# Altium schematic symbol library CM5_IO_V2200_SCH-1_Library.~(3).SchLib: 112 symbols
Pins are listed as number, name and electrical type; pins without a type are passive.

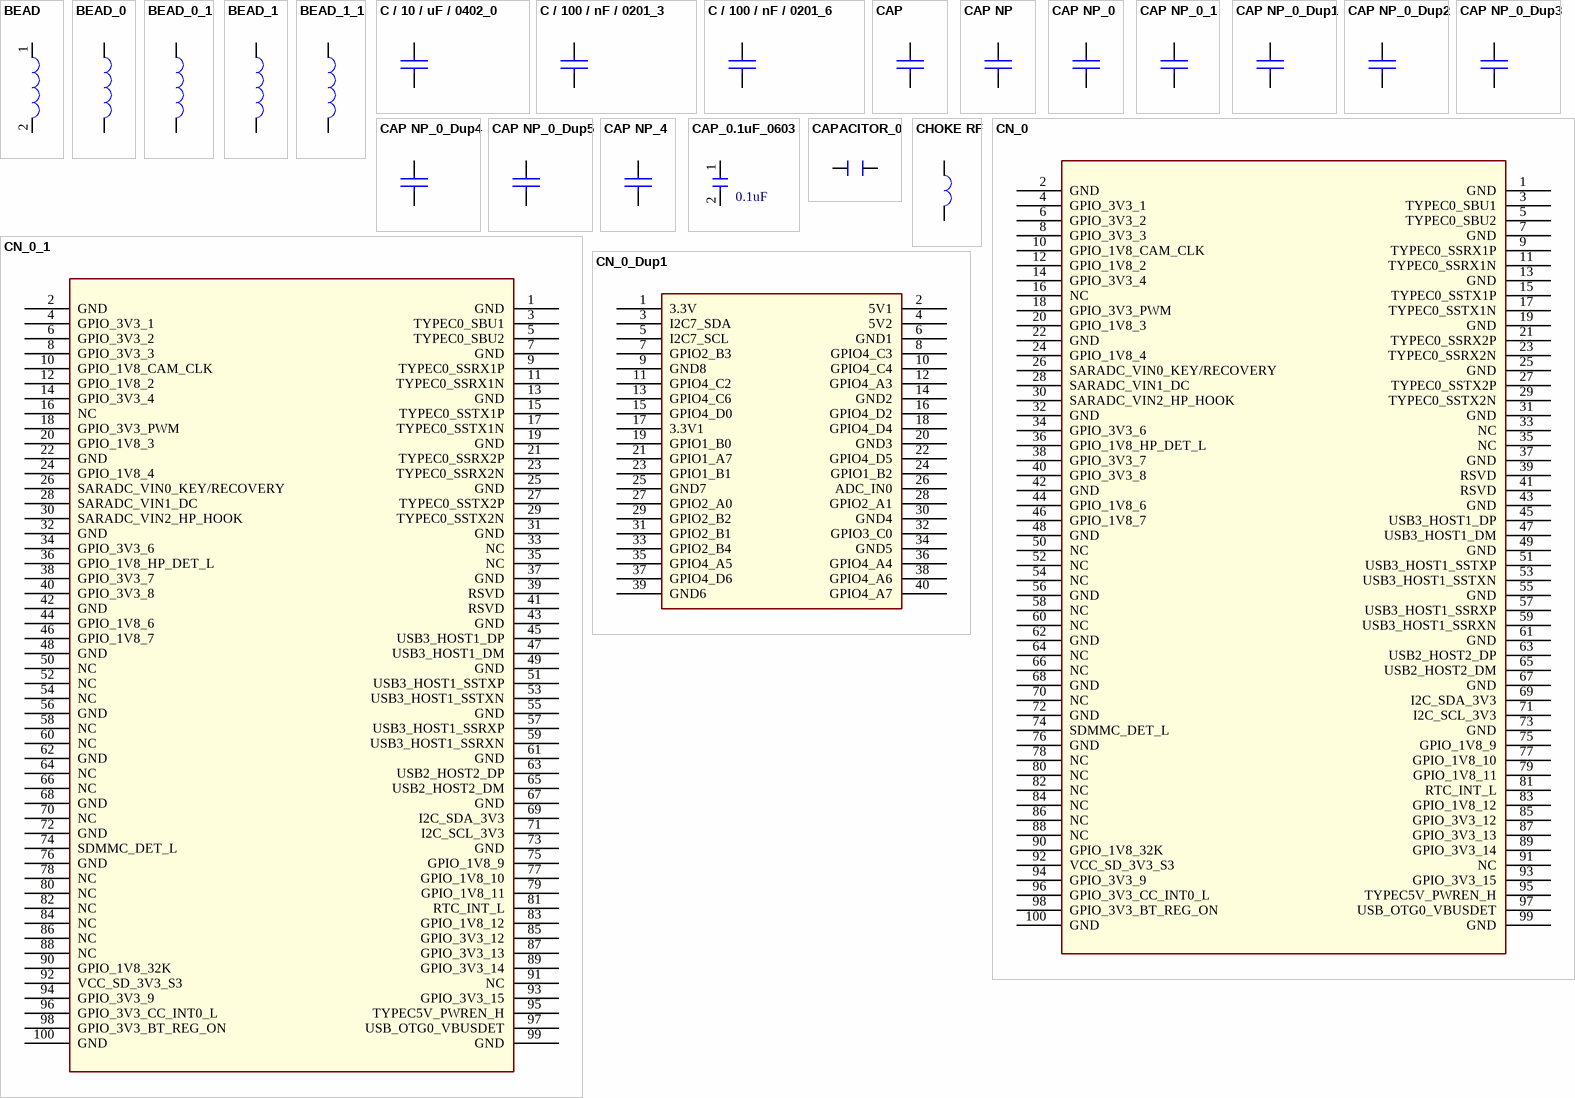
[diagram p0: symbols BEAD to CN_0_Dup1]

## BEAD
designator FB?
Altium-Right: 20; Altium-Bottom: 40
pins: 1, 2

## BEAD_0
designator FB?
Altium-Right: 20; Altium-Bottom: 40
pins: 1, 2

## BEAD_0_1
designator FB?
Altium-Right: 20; Altium-Bottom: 40
pins: 1, 2

## BEAD_1
designator FB?
Altium-Right: 20; Altium-Bottom: 40
pins: 1, 2

## BEAD_1_1
designator FB?
Altium-Right: 20; Altium-Bottom: 40
pins: 1, 2

## C / 10 / uF / 0402_0
designator C?
Altium-Right: 20; Altium-Bottom: 10
footprint C0402
pins: 1, 2

## C / 100 / nF / 0201_3
designator C?
Altium-Right: 20; Altium-Bottom: 10
footprint C0201
pins: 1, 2

## C / 100 / nF / 0201_6
designator C?
Altium-Right: 20; Altium-Bottom: 10
footprint C0201
pins: 1, 2

## CAP
designator C?
Altium-Right: 20; Altium-Bottom: 10
pins: 1, 2

## CAP NP
designator C?
Altium-Right: 20; Altium-Bottom: 10
footprint C0402
pins: 1, 2

## CAP NP_0
designator C?
Altium-Right: 20; Altium-Bottom: 10
pins: 1, 2

## CAP NP_0_1
designator C?
Altium-Right: 20; Altium-Bottom: 10
pins: 1, 2

## CAP NP_0_Dup1
designator C?
Altium-Right: 20; Altium-Bottom: 10
pins: 1, 2

## CAP NP_0_Dup2
designator C?
Altium-Right: 20; Altium-Bottom: 10
pins: 1, 2

## CAP NP_0_Dup3
designator C?
Altium-Right: 20; Altium-Bottom: 10
pins: 1, 2

## CAP NP_0_Dup4
designator C?
Altium-Right: 20; Altium-Bottom: 10
pins: 1, 2

## CAP NP_0_Dup5
designator C?
Altium-Right: 20; Altium-Bottom: 10
pins: 1, 2

## CAP NP_4
designator C?
Altium-Right: 20; Altium-Bottom: 10
pins: 1, 2

## CAP_0.1uF_0603
designator CB?, comment 0.1uF
Altium-Right: 20; Altium-Bottom: 10
footprint C0603
pins: 1, 2

## CAPACITOR_0
designator C?
Altium-Right: 10; Altium-Bottom: 20
pins: 1, 2

## CHOKE RF
designator L?
Altium-Right: 20
pins: 1, 2

## CN_0
designator CN?
Altium-Right: 296; Altium-Bottom: 529
pins: 1 GND, 2 GND, 3 TYPEC0_SBU1, 4 GPIO_3V3_1, 5 TYPEC0_SBU2, 6 GPIO_3V3_2, 7 GND, 8 GPIO_3V3_3, 9 TYPEC0_SSRX1P, 10 GPIO_1V8_CAM_CLK, 11 TYPEC0_SSRX1N, 12 GPIO_1V8_2, 13 GND, 14 GPIO_3V3_4, 15 TYPEC0_SSTX1P, 16 NC, 17 TYPEC0_SSTX1N, 18 GPIO_3V3_PWM, 19 GND, 20 GPIO_1V8_3, 21 TYPEC0_SSRX2P, 22 GND, 23 TYPEC0_SSRX2N, 24 GPIO_1V8_4, 25 GND, 26 SARADC_VIN0_KEY/RECOVERY, 27 TYPEC0_SSTX2P, 28 SARADC_VIN1_DC, 29 TYPEC0_SSTX2N, 30 SARADC_VIN2_HP_HOOK, 31 GND, 32 GND, 33 NC, 34 GPIO_3V3_6, 35 NC, 36 GPIO_1V8_HP_DET_L, 37 GND, 38 GPIO_3V3_7, 39 RSVD, 40 GPIO_3V3_8, 41 RSVD, 42 GND, 43 GND, 44 GPIO_1V8_6, 45 USB3_HOST1_DP, 46 GPIO_1V8_7, 47 USB3_HOST1_DM, 48 GND, 49 GND, 50 NC, 51 USB3_HOST1_SSTXP, 52 NC, 53 USB3_HOST1_SSTXN, 54 NC, 55 GND, 56 GND, 57 USB3_HOST1_SSRXP, 58 NC, 59 USB3_HOST1_SSRXN, 60 NC, 61 GND, 62 GND, 63 USB2_HOST2_DP, 64 NC, 65 USB2_HOST2_DM, 66 NC, 67 GND, 68 GND, 69 I2C_SDA_3V3, 70 NC, 71 I2C_SCL_3V3, 72 GND, 73 GND, 74 SDMMC_DET_L, 75 GPIO_1V8_9, 76 GND, 77 GPIO_1V8_10, 78 NC, 79 GPIO_1V8_11, 80 NC, 81 RTC_INT_L, 82 NC, 83 GPIO_1V8_12, 84 NC, 85 GPIO_3V3_12, 86 NC, 87 GPIO_3V3_13, 88 NC, 89 GPIO_3V3_14, 90 GPIO_1V8_32K, 91 NC, 92 VCC_SD_3V3_S3, 93 GPIO_3V3_15, 94 GPIO_3V3_9, 95 TYPEC5V_PWREN_H, 96 GPIO_3V3_CC_INT0_L, 97 USB_OTG0_VBUSDET, 98 GPIO_3V3_BT_REG_ON, 99 GND, 100 GND

## CN_0_1
designator CN?
Altium-Right: 296; Altium-Bottom: 529
pins: 1 GND, 2 GND, 3 TYPEC0_SBU1, 4 GPIO_3V3_1, 5 TYPEC0_SBU2, 6 GPIO_3V3_2, 7 GND, 8 GPIO_3V3_3, 9 TYPEC0_SSRX1P, 10 GPIO_1V8_CAM_CLK, 11 TYPEC0_SSRX1N, 12 GPIO_1V8_2, 13 GND, 14 GPIO_3V3_4, 15 TYPEC0_SSTX1P, 16 NC, 17 TYPEC0_SSTX1N, 18 GPIO_3V3_PWM, 19 GND, 20 GPIO_1V8_3, 21 TYPEC0_SSRX2P, 22 GND, 23 TYPEC0_SSRX2N, 24 GPIO_1V8_4, 25 GND, 26 SARADC_VIN0_KEY/RECOVERY, 27 TYPEC0_SSTX2P, 28 SARADC_VIN1_DC, 29 TYPEC0_SSTX2N, 30 SARADC_VIN2_HP_HOOK, 31 GND, 32 GND, 33 NC, 34 GPIO_3V3_6, 35 NC, 36 GPIO_1V8_HP_DET_L, 37 GND, 38 GPIO_3V3_7, 39 RSVD, 40 GPIO_3V3_8, 41 RSVD, 42 GND, 43 GND, 44 GPIO_1V8_6, 45 USB3_HOST1_DP, 46 GPIO_1V8_7, 47 USB3_HOST1_DM, 48 GND, 49 GND, 50 NC, 51 USB3_HOST1_SSTXP, 52 NC, 53 USB3_HOST1_SSTXN, 54 NC, 55 GND, 56 GND, 57 USB3_HOST1_SSRXP, 58 NC, 59 USB3_HOST1_SSRXN, 60 NC, 61 GND, 62 GND, 63 USB2_HOST2_DP, 64 NC, 65 USB2_HOST2_DM, 66 NC, 67 GND, 68 GND, 69 I2C_SDA_3V3, 70 NC, 71 I2C_SCL_3V3, 72 GND, 73 GND, 74 SDMMC_DET_L, 75 GPIO_1V8_9, 76 GND, 77 GPIO_1V8_10, 78 NC, 79 GPIO_1V8_11, 80 NC, 81 RTC_INT_L, 82 NC, 83 GPIO_1V8_12, 84 NC, 85 GPIO_3V3_12, 86 NC, 87 GPIO_3V3_13, 88 NC, 89 GPIO_3V3_14, 90 GPIO_1V8_32K, 91 NC, 92 VCC_SD_3V3_S3, 93 GPIO_3V3_15, 94 GPIO_3V3_9, 95 TYPEC5V_PWREN_H, 96 GPIO_3V3_CC_INT0_L, 97 USB_OTG0_VBUSDET, 98 GPIO_3V3_BT_REG_ON, 99 GND, 100 GND

## CN_0_Dup1
designator CN?
Altium-Right: 160; Altium-Bottom: 210
pins: 1 3.3V, 2 5V1, 3 I2C7_SDA, 4 5V2, 5 I2C7_SCL, 6 GND1, 7 GPIO2_B3, 8 GPIO4_C3, 9 GND8, 10 GPIO4_C4, 11 GPIO4_C2, 12 GPIO4_A3, 13 GPIO4_C6, 14 GND2, 15 GPIO4_D0, 16 GPIO4_D2, 17 3.3V1, 18 GPIO4_D4, 19 GPIO1_B0, 20 GND3, 21 GPIO1_A7, 22 GPIO4_D5, 23 GPIO1_B1, 24 GPIO1_B2, 25 GND7, 26 ADC_IN0, 27 GPIO2_A0, 28 GPIO2_A1, 29 GPIO2_B2, 30 GND4, 31 GPIO2_B1, 32 GPIO3_C0, 33 GPIO2_B4, 34 GND5, 35 GPIO4_A5, 36 GPIO4_A4, 37 GPIO4_D6, 38 GPIO4_A6, 39 GND6, 40 GPIO4_A7

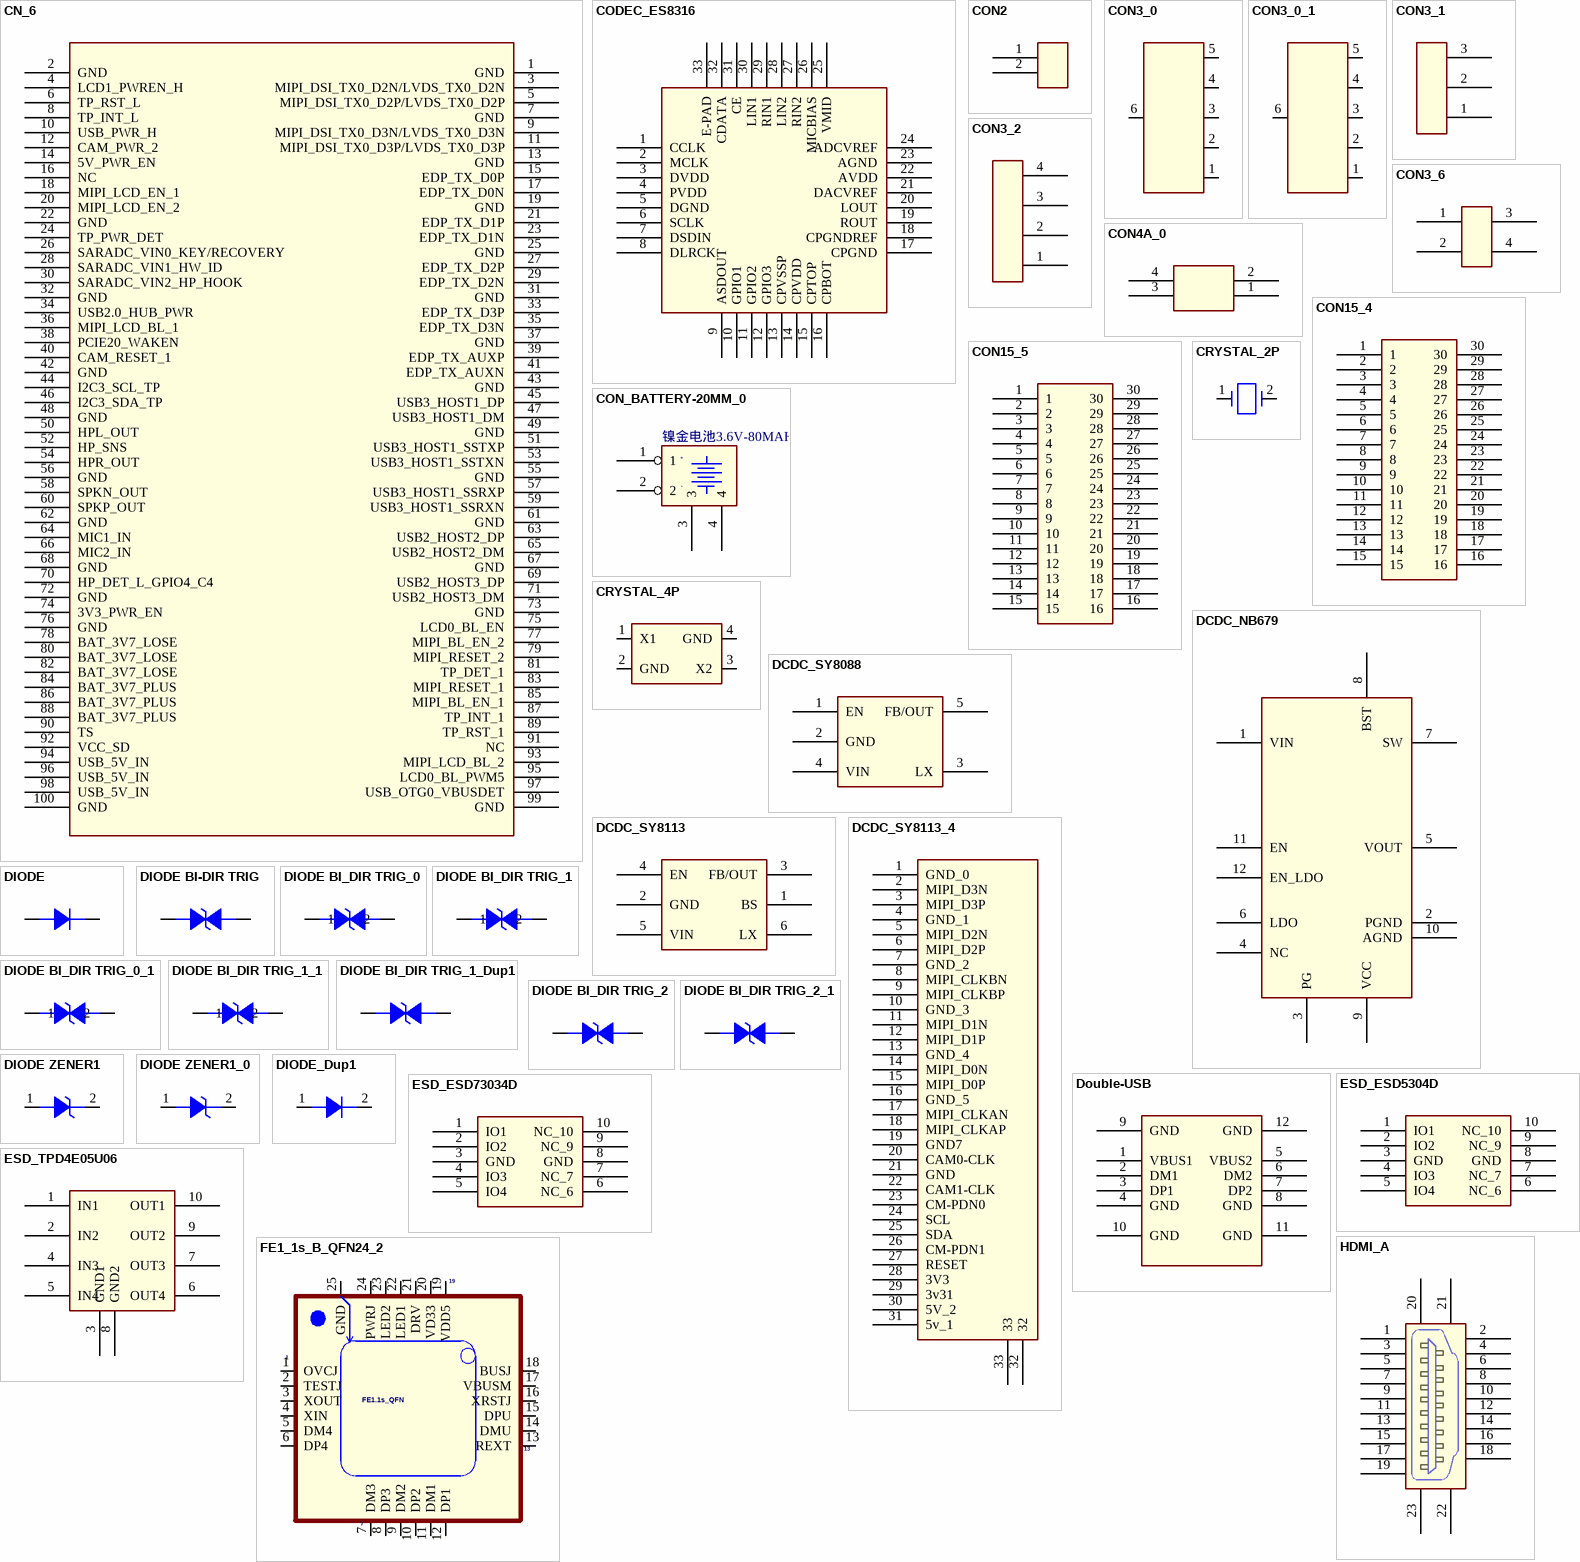
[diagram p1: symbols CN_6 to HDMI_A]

## CN_6
designator CN?
Altium-Right: 296; Altium-Bottom: 529
pins: 1 GND, 2 GND, 3 MIPI_DSI_TX0_D2N/LVDS_TX0_D2N, 4 LCD1_PWREN_H, 5 MIPI_DSI_TX0_D2P/LVDS_TX0_D2P, 6 TP_RST_L, 7 GND, 8 TP_INT_L, 9 MIPI_DSI_TX0_D3N/LVDS_TX0_D3N, 10 USB_PWR_H, 11 MIPI_DSI_TX0_D3P/LVDS_TX0_D3P, 12 CAM_PWR_2, 13 GND, 14 5V_PWR_EN, 15 EDP_TX_D0P, 16 NC, 17 EDP_TX_D0N, 18 MIPI_LCD_EN_1, 19 GND, 20 MIPI_LCD_EN_2, 21 EDP_TX_D1P, 22 GND, 23 EDP_TX_D1N, 24 TP_PWR_DET, 25 GND, 26 SARADC_VIN0_KEY/RECOVERY, 27 EDP_TX_D2P, 28 SARADC_VIN1_HW_ID, 29 EDP_TX_D2N, 30 SARADC_VIN2_HP_HOOK, 31 GND, 32 GND, 33 EDP_TX_D3P, 34 USB2.0_HUB_PWR, 35 EDP_TX_D3N, 36 MIPI_LCD_BL_1, 37 GND, 38 PCIE20_WAKEN, 39 EDP_TX_AUXP, 40 CAM_RESET_1, 41 EDP_TX_AUXN, 42 GND, 43 GND, 44 I2C3_SCL_TP, 45 USB3_HOST1_DP, 46 I2C3_SDA_TP, 47 USB3_HOST1_DM, 48 GND, 49 GND, 50 HPL_OUT, 51 USB3_HOST1_SSTXP, 52 HP_SNS, 53 USB3_HOST1_SSTXN, 54 HPR_OUT, 55 GND, 56 GND, 57 USB3_HOST1_SSRXP, 58 SPKN_OUT, 59 USB3_HOST1_SSRXN, 60 SPKP_OUT, 61 GND, 62 GND, 63 USB2_HOST2_DP, 64 MIC1_IN, 65 USB2_HOST2_DM, 66 MIC2_IN, 67 GND, 68 GND, 69 USB2_HOST3_DP, 70 HP_DET_L_GPIO4_C4, 71 USB2_HOST3_DM, 72 GND, 73 GND, 74 3V3_PWR_EN, 75 LCD0_BL_EN, 76 GND, 77 MIPI_BL_EN_2, 78 BAT_3V7_LOSE, 79 MIPI_RESET_2, 80 BAT_3V7_LOSE, 81 TP_DET_1, 82 BAT_3V7_LOSE, 83 MIPI_RESET_1, 84 BAT_3V7_PLUS, 85 MIPI_BL_EN_1, 86 BAT_3V7_PLUS, 87 TP_INT_1, 88 BAT_3V7_PLUS, 89 TP_RST_1, 90 TS, 91 NC, 92 VCC_SD, 93 MIPI_LCD_BL_2, 94 USB_5V_IN, 95 LCD0_BL_PWM5, 96 USB_5V_IN, 97 USB_OTG0_VBUSDET, 98 USB_5V_IN, 99 GND, 100 GND

## CODEC_ES8316
designator U?
Altium-Right: 150
pins: 1 CCLK, 2 MCLK, 3 DVDD, 4 PVDD, 5 DGND, 6 SCLK, 7 DSDIN, 8 DLRCK, 9 ASDOUT, 10 GPIO1, 11 GPIO2, 12 GPIO3, 13 CPVSSP, 14 CPVDD, 15 CPTOP, 16 CPBOT, 17 CPGND, 18 CPGNDREF, 19 ROUT, 20 LOUT, 21 DACVREF, 22 AVDD, 23 AGND, 24 ADCVREF, 25 VMID, 26 MICBIAS, 27 RIN2, 28 LIN2, 29 RIN1, 30 LIN1, 31 CE, 32 CDATA, 33 E-PAD

## CON2
designator J?
Altium-Right: 20; Altium-Bottom: 30
pins: 1, 2

## CON3_0
designator J?
Altium-Right: 40; Altium-Bottom: 100
pins: 1, 2, 3, 4, 5, 6

## CON3_0_1
designator J?
Altium-Right: 40; Altium-Bottom: 100
pins: 1, 2, 3, 4, 5, 6

## CON3_1
designator J?
Altium-Right: 20; Altium-Bottom: 61
pins: 1, 2, 3

## CON3_2
designator J?
Altium-Right: 20; Altium-Bottom: 81
pins: 1, 2, 3, 4

## CON3_6
designator J?
Altium-Right: 20; Altium-Bottom: 40
pins: 1, 2, 3, 4

## CON4A_0
designator J?
Altium-Right: 40; Altium-Bottom: 30
pins: 1, 2, 3, 4

## CON15_4
designator J?
Altium-Right: 50; Altium-Bottom: 160
pins: 1, 2, 3, 4, 5, 6, 7, 8, 9, 10, 11, 12, 13, 14, 15, 16, 17, 18, 19, 20, 21, 22, 23, 24, 25, 26, 27, 28, 29, 30

## CON15_5
designator J?
Altium-Right: 50; Altium-Bottom: 160
pins: 1, 2, 3, 4, 5, 6, 7, 8, 9, 10, 11, 12, 13, 14, 15, 16, 17, 18, 19, 20, 21, 22, 23, 24, 25, 26, 27, 28, 29, 30

## CON_BATTERY-20MM_0
designator U?, comment 镍金电池3.6V-80MAH
Altium-Right: 50; Altium-Bottom: 40
footprint BATTERY-20MM
pins: 1, 2, 3, 4

## CRYSTAL_2P
designator Y?
Altium-Right: 20
pins: 1, 2

## CRYSTAL_4P
designator Y?
Altium-Right: 60; Altium-Bottom: 40
footprint CRY-3225
pins: 1 X1, 2 GND (power), 3 X2, 4 GND (power)

## DCDC_NB679
designator U?
Altium-Right: 100; Altium-Bottom: 200
footprint QFN12_3R00X2R00X0R90
pins: 1 VIN, 2 PGND, 3 PG, 4 NC, 5 VOUT, 6 LDO, 7 SW, 8 BST, 9 VCC, 10 AGND, 11 EN, 12 EN_LDO

## DCDC_SY8088
designator U?
Altium-Right: 70; Altium-Bottom: 60
pins: 1 EN, 2 GND, 3 LX, 4 VIN, 5 FB/OUT

## DCDC_SY8113
designator U?
Altium-Right: 70; Altium-Bottom: 60
pins: 1 BS, 2 GND, 3 FB/OUT, 4 EN, 5 VIN, 6 LX

## DCDC_SY8113_4
designator U?
Altium-Right: 80; Altium-Bottom: 320
pins: 1 GND_0, 2 MIPI_D3N, 3 MIPI_D3P, 4 GND_1, 5 MIPI_D2N, 6 MIPI_D2P, 7 GND_2, 8 MIPI_CLKBN, 9 MIPI_CLKBP, 10 GND_3, 11 MIPI_D1N, 12 MIPI_D1P, 13 GND_4, 14 MIPI_D0N, 15 MIPI_D0P, 16 GND_5, 17 MIPI_CLKAN, 18 MIPI_CLKAP, 19 GND7, 20 CAM0-CLK, 21 GND, 22 CAM1-CLK, 23 CM-PDN0, 24 SCL, 25 SDA, 26 CM-PDN1, 27 RESET, 28 3V3, 29 3v31, 30 5V_2, 31 5v_1, 32, 33

## DIODE
designator D?
Altium-Right: 30; Altium-Bottom: 20
pins: 1 A, 2 K

## DIODE BI-DIR TRIG
designator D?
Altium-Right: 40; Altium-Bottom: 20
pins: 1, 2

## DIODE BI_DIR TRIG_0
designator ED?
Altium-Right: 40; Altium-Bottom: 20
pins: 1, 2

## DIODE BI_DIR TRIG_0_1
designator ED?
Altium-Right: 40; Altium-Bottom: 20
pins: 1, 2

## DIODE BI_DIR TRIG_1
designator ED?
Altium-Right: 40; Altium-Bottom: 20
pins: 1, 2

## DIODE BI_DIR TRIG_1_1
designator ED?
Altium-Right: 40; Altium-Bottom: 20
pins: 1, 2

## DIODE BI_DIR TRIG_1_Dup1
designator ED?
Altium-Right: 40; Altium-Bottom: 20
pins: 1, 2

## DIODE BI_DIR TRIG_2
designator ED?
Altium-Right: 40; Altium-Bottom: 20
pins: 1, 2

## DIODE BI_DIR TRIG_2_1
designator ED?
Altium-Right: 40; Altium-Bottom: 20
pins: 1, 2

## DIODE ZENER1
designator D?
Altium-Right: 30; Altium-Bottom: 20
pins: 1 ANODE, 2 CATHODE

## DIODE ZENER1_0
designator D?
Altium-Right: 30; Altium-Bottom: 20
pins: 1 ANODE, 2 CATHODE

## DIODE_Dup1
designator D?
Altium-Right: 30; Altium-Bottom: 20
pins: 1 A, 2 K

## Double-USB
designator U?
Altium-Right: 80; Altium-Bottom: 100
footprint USB_DUAL
pins: 1 VBUS1, 2 DM1, 3 DP1, 4 GND, 5 VBUS2, 6 DM2, 7 DP2, 8 GND, 9 GND, 10 GND, 11 GND, 12 GND

## ESD_ESD5304D
designator U?
Altium-Right: 70; Altium-Bottom: 60
pins: 1 IO1, 2 IO2, 3 GND (power), 4 IO3, 5 IO4, 6 NC_6, 7 NC_7, 8 GND (power), 9 NC_9, 10 NC_10

## ESD_ESD73034D
designator U?
Altium-Right: 70; Altium-Bottom: 60
pins: 1 IO1, 2 IO2, 3 GND (power), 4 IO3, 5 IO4, 6 NC_6, 7 NC_7, 8 GND (power), 9 NC_9, 10 NC_10

## ESD_TPD4E05U06
designator U?
Altium-Right: 70; Altium-Bottom: 80
pins: 1 IN1, 2 IN2, 3 GND1, 4 IN3, 5 IN4, 6 OUT4, 7 OUT3, 8 GND2, 9 OUT2, 10 OUT1

## FE1_1s_B_QFN24_2
designator U?, comment FE1.1s_QFN
Altium-Right: 150
pins: 1 OVCJ, 2 TESTJ, 3 XOUT, 4 XIN, 5 DM4, 6 DP4, 7 DM3, 8 DP3, 9 DM2, 10 DP2, 11 DM1, 12 DP1, 13 REXT, 14 DMU, 15 DPU, 16 XRSTJ, 17 VBUSM, 18 BUSJ, 19 VDD5, 20 VD33, 21 DRV, 22 LED1, 23 LED2, 24 PWRJ, 25 GND (power)

## HDMI_A
designator J?
Altium-Right: 40; Altium-Bottom: 110
pins: 1 $PIN0, 2, 3, 4, 5, 6, 7, 8, 9, 10, 11, 12, 13, 14, 15, 16, 17, 18, 19, 20, 21, 22, 23

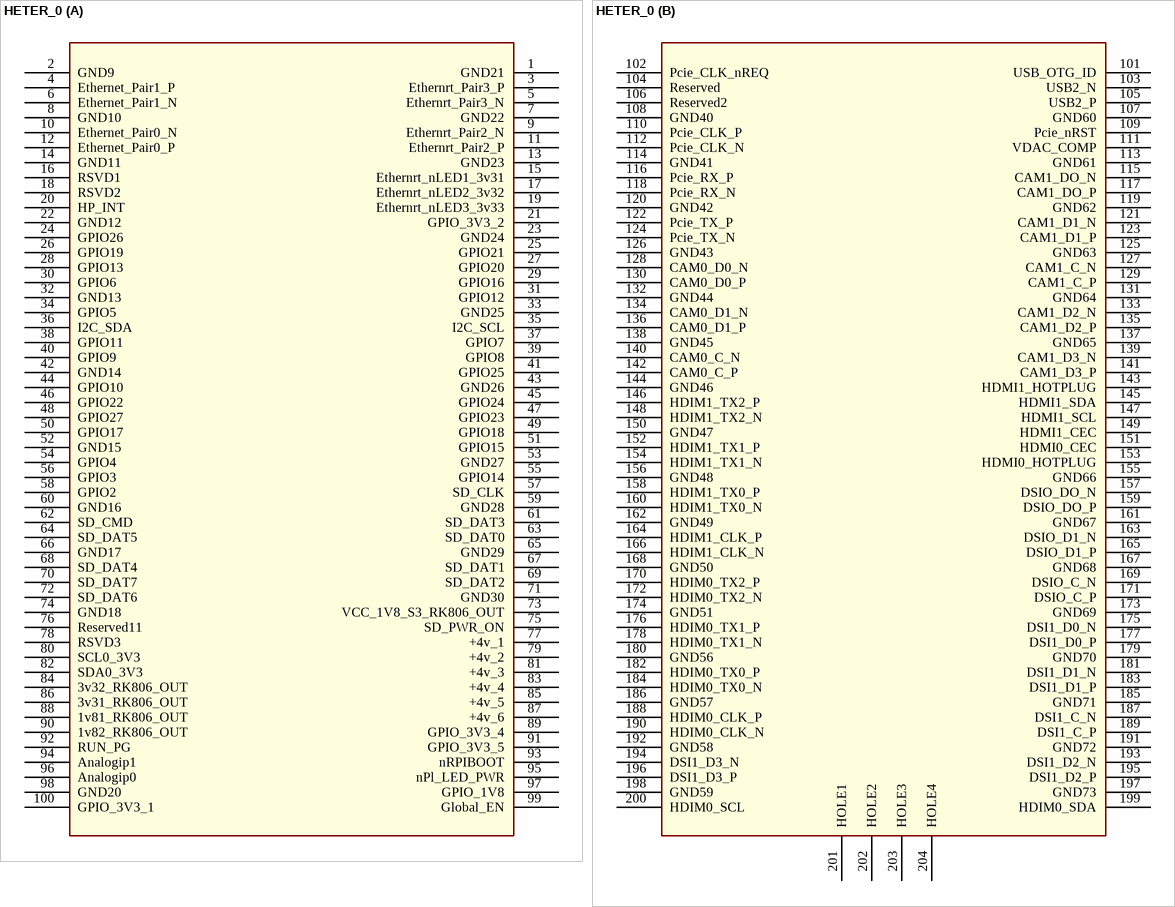
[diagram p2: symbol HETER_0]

## HETER_0
designator U?
Altium-Right: 296; Altium-Bottom: 529
part A pins: 1 GND21, 2 GND9, 3 Ethernrt_Pair3_P, 4 Ethernet_Pair1_P, 5 Ethernrt_Pair3_N, 6 Ethernet_Pair1_N, 7 GND22, 8 GND10, 9 Ethernrt_Pair2_N, 10 Ethernet_Pair0_N, 11 Ethernrt_Pair2_P, 12 Ethernet_Pair0_P, 13 GND23, 14 GND11, 15 Ethernrt_nLED1_3v31, 16 RSVD1, 17 Ethernrt_nLED2_3v32, 18 RSVD2, 19 Ethernrt_nLED3_3v33, 20 HP_INT, 21 GPIO_3V3_2, 22 GND12, 23 GND24, 24 GPIO26, 25 GPIO21, 26 GPIO19, 27 GPIO20, 28 GPIO13, 29 GPIO16, 30 GPIO6, 31 GPIO12, 32 GND13, 33 GND25, 34 GPIO5, 35 I2C_SCL, 36 I2C_SDA, 37 GPIO7, 38 GPIO11, 39 GPIO8, 40 GPIO9, 41 GPIO25, 42 GND14, 43 GND26, 44 GPIO10, 45 GPIO24, 46 GPIO22, 47 GPIO23, 48 GPIO27, 49 GPIO18, 50 GPIO17, 51 GPIO15, 52 GND15, 53 GND27, 54 GPIO4, 55 GPIO14, 56 GPIO3, 57 SD_CLK, 58 GPIO2, 59 GND28, 60 GND16, 61 SD_DAT3, 62 SD_CMD, 63 SD_DAT0, 64 SD_DAT5, 65 GND29, 66 GND17, 67 SD_DAT1, 68 SD_DAT4, 69 SD_DAT2, 70 SD_DAT7, 71 GND30, 72 SD_DAT6, 73 VCC_1V8_S3_RK806_OUT, 74 GND18, 75 SD_PWR_ON, 76 Reserved11, 77 +4v_1, 78 RSVD3, 79 +4v_2, 80 SCL0_3V3, 81 +4v_3, 82 SDA0_3V3, 83 +4v_4, 84 3v32_RK806_OUT, 85 +4v_5, 86 3v31_RK806_OUT, 87 +4v_6, 88 1v81_RK806_OUT, 89 GPIO_3V3_4, 90 1v82_RK806_OUT, 91 GPIO_3V3_5, 92 RUN_PG, 93 nRPIBOOT, 94 Analogip1, 95 nPl_LED_PWR, 96 Analogip0, 97 GPIO_1V8, 98 GND20, 99 Global_EN, 100 GPIO_3V3_1
part B pins: 101 USB_OTG_ID, 102 Pcie_CLK_nREQ, 103 USB2_N, 104 Reserved, 105 USB2_P, 106 Reserved2, 107 GND60, 108 GND40, 109 Pcie_nRST, 110 Pcie_CLK_P, 111 VDAC_COMP, 112 Pcie_CLK_N, 113 GND61, 114 GND41, 115 CAM1_DO_N, 116 Pcie_RX_P, 117 CAM1_DO_P, 118 Pcie_RX_N, 119 GND62, 120 GND42, 121 CAM1_D1_N, 122 Pcie_TX_P, 123 CAM1_D1_P, 124 Pcie_TX_N, 125 GND63, 126 GND43, 127 CAM1_C_N, 128 CAM0_D0_N, 129 CAM1_C_P, 130 CAM0_D0_P, 131 GND64, 132 GND44, 133 CAM1_D2_N, 134 CAM0_D1_N, 135 CAM1_D2_P, 136 CAM0_D1_P, 137 GND65, 138 GND45, 139 CAM1_D3_N, 140 CAM0_C_N, 141 CAM1_D3_P, 142 CAM0_C_P, 143 HDMI1_HOTPLUG, 144 GND46, 145 HDMI1_SDA, 146 HDIM1_TX2_P, 147 HDMI1_SCL, 148 HDIM1_TX2_N, 149 HDMI1_CEC, 150 GND47, 151 HDMI0_CEC, 152 HDIM1_TX1_P, 153 HDMI0_HOTPLUG, 154 HDIM1_TX1_N, 155 GND66, 156 GND48, 157 DSIO_DO_N, 158 HDIM1_TX0_P, 159 DSIO_DO_P, 160 HDIM1_TX0_N, 161 GND67, 162 GND49, 163 DSIO_D1_N, 164 HDIM1_CLK_P, 165 DSIO_D1_P, 166 HDIM1_CLK_N, 167 GND68, 168 GND50, 169 DSIO_C_N, 170 HDIM0_TX2_P, 171 DSIO_C_P, 172 HDIM0_TX2_N, 173 GND69, 174 GND51, 175 DSI1_D0_N, 176 HDIM0_TX1_P, 177 DSI1_D0_P, 178 HDIM0_TX1_N, 179 GND70, 180 GND56, 181 DSI1_D1_N, 182 HDIM0_TX0_P, 183 DSI1_D1_P, 184 HDIM0_TX0_N, 185 GND71, 186 GND57, 187 DSI1_C_N, 188 HDIM0_CLK_P, 189 DSI1_C_P, 190 HDIM0_CLK_N, 191 GND72, 192 GND58, 193 DSI1_D2_N, 194 DSI1_D3_N, 195 DSI1_D2_P, 196 DSI1_D3_P, 197 GND73, 198 GND59, 199 HDIM0_SDA, 200 HDIM0_SCL, 201 HOLE1, 202 HOLE2, 203 HOLE3, 204 HOLE4

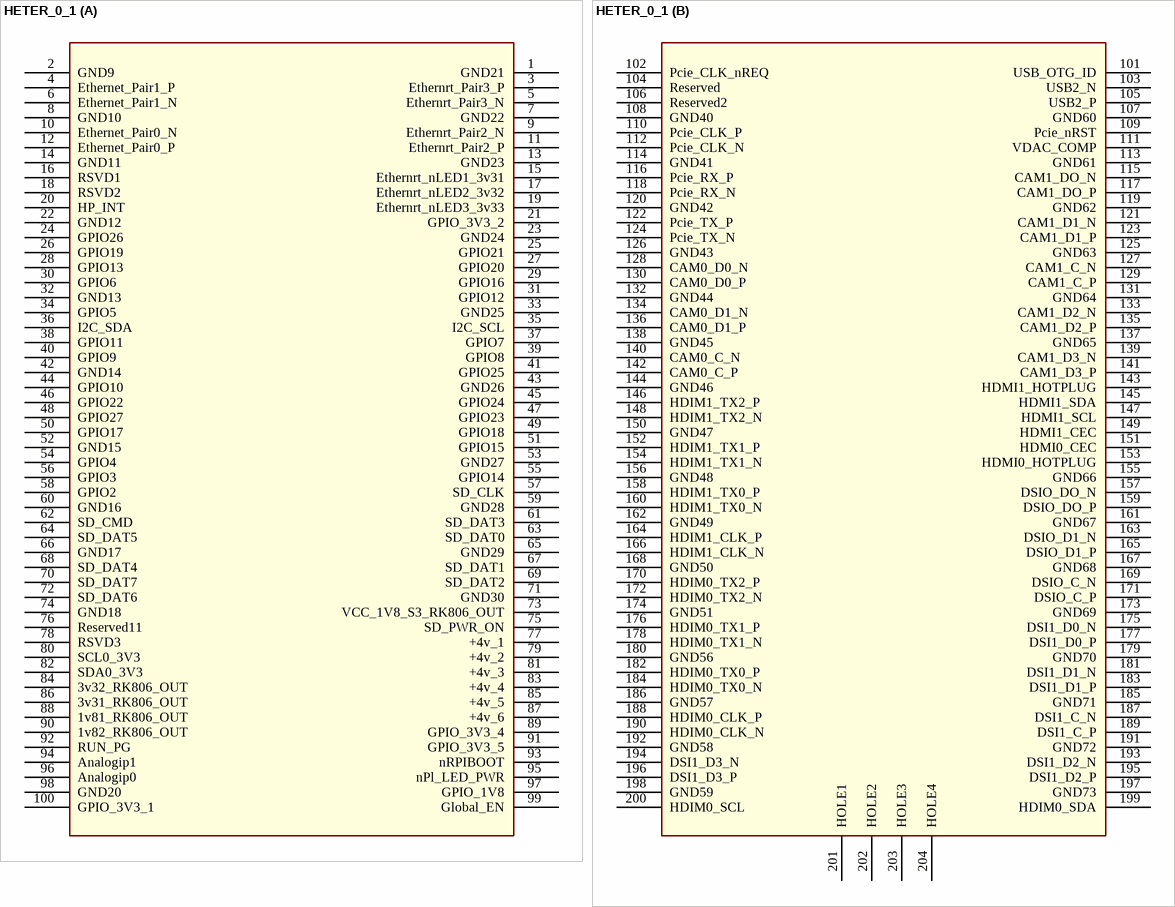
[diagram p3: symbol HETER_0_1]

## HETER_0_1
designator U?
Altium-Right: 296; Altium-Bottom: 529
part A pins: 1 GND21, 2 GND9, 3 Ethernrt_Pair3_P, 4 Ethernet_Pair1_P, 5 Ethernrt_Pair3_N, 6 Ethernet_Pair1_N, 7 GND22, 8 GND10, 9 Ethernrt_Pair2_N, 10 Ethernet_Pair0_N, 11 Ethernrt_Pair2_P, 12 Ethernet_Pair0_P, 13 GND23, 14 GND11, 15 Ethernrt_nLED1_3v31, 16 RSVD1, 17 Ethernrt_nLED2_3v32, 18 RSVD2, 19 Ethernrt_nLED3_3v33, 20 HP_INT, 21 GPIO_3V3_2, 22 GND12, 23 GND24, 24 GPIO26, 25 GPIO21, 26 GPIO19, 27 GPIO20, 28 GPIO13, 29 GPIO16, 30 GPIO6, 31 GPIO12, 32 GND13, 33 GND25, 34 GPIO5, 35 I2C_SCL, 36 I2C_SDA, 37 GPIO7, 38 GPIO11, 39 GPIO8, 40 GPIO9, 41 GPIO25, 42 GND14, 43 GND26, 44 GPIO10, 45 GPIO24, 46 GPIO22, 47 GPIO23, 48 GPIO27, 49 GPIO18, 50 GPIO17, 51 GPIO15, 52 GND15, 53 GND27, 54 GPIO4, 55 GPIO14, 56 GPIO3, 57 SD_CLK, 58 GPIO2, 59 GND28, 60 GND16, 61 SD_DAT3, 62 SD_CMD, 63 SD_DAT0, 64 SD_DAT5, 65 GND29, 66 GND17, 67 SD_DAT1, 68 SD_DAT4, 69 SD_DAT2, 70 SD_DAT7, 71 GND30, 72 SD_DAT6, 73 VCC_1V8_S3_RK806_OUT, 74 GND18, 75 SD_PWR_ON, 76 Reserved11, 77 +4v_1, 78 RSVD3, 79 +4v_2, 80 SCL0_3V3, 81 +4v_3, 82 SDA0_3V3, 83 +4v_4, 84 3v32_RK806_OUT, 85 +4v_5, 86 3v31_RK806_OUT, 87 +4v_6, 88 1v81_RK806_OUT, 89 GPIO_3V3_4, 90 1v82_RK806_OUT, 91 GPIO_3V3_5, 92 RUN_PG, 93 nRPIBOOT, 94 Analogip1, 95 nPl_LED_PWR, 96 Analogip0, 97 GPIO_1V8, 98 GND20, 99 Global_EN, 100 GPIO_3V3_1
part B pins: 101 USB_OTG_ID, 102 Pcie_CLK_nREQ, 103 USB2_N, 104 Reserved, 105 USB2_P, 106 Reserved2, 107 GND60, 108 GND40, 109 Pcie_nRST, 110 Pcie_CLK_P, 111 VDAC_COMP, 112 Pcie_CLK_N, 113 GND61, 114 GND41, 115 CAM1_DO_N, 116 Pcie_RX_P, 117 CAM1_DO_P, 118 Pcie_RX_N, 119 GND62, 120 GND42, 121 CAM1_D1_N, 122 Pcie_TX_P, 123 CAM1_D1_P, 124 Pcie_TX_N, 125 GND63, 126 GND43, 127 CAM1_C_N, 128 CAM0_D0_N, 129 CAM1_C_P, 130 CAM0_D0_P, 131 GND64, 132 GND44, 133 CAM1_D2_N, 134 CAM0_D1_N, 135 CAM1_D2_P, 136 CAM0_D1_P, 137 GND65, 138 GND45, 139 CAM1_D3_N, 140 CAM0_C_N, 141 CAM1_D3_P, 142 CAM0_C_P, 143 HDMI1_HOTPLUG, 144 GND46, 145 HDMI1_SDA, 146 HDIM1_TX2_P, 147 HDMI1_SCL, 148 HDIM1_TX2_N, 149 HDMI1_CEC, 150 GND47, 151 HDMI0_CEC, 152 HDIM1_TX1_P, 153 HDMI0_HOTPLUG, 154 HDIM1_TX1_N, 155 GND66, 156 GND48, 157 DSIO_DO_N, 158 HDIM1_TX0_P, 159 DSIO_DO_P, 160 HDIM1_TX0_N, 161 GND67, 162 GND49, 163 DSIO_D1_N, 164 HDIM1_CLK_P, 165 DSIO_D1_P, 166 HDIM1_CLK_N, 167 GND68, 168 GND50, 169 DSIO_C_N, 170 HDIM0_TX2_P, 171 DSIO_C_P, 172 HDIM0_TX2_N, 173 GND69, 174 GND51, 175 DSI1_D0_N, 176 HDIM0_TX1_P, 177 DSI1_D0_P, 178 HDIM0_TX1_N, 179 GND70, 180 GND56, 181 DSI1_D1_N, 182 HDIM0_TX0_P, 183 DSI1_D1_P, 184 HDIM0_TX0_N, 185 GND71, 186 GND57, 187 DSI1_C_N, 188 HDIM0_CLK_P, 189 DSI1_C_P, 190 HDIM0_CLK_N, 191 GND72, 192 GND58, 193 DSI1_D2_N, 194 DSI1_D3_N, 195 DSI1_D2_P, 196 DSI1_D3_P, 197 GND73, 198 GND59, 199 HDIM0_SDA, 200 HDIM0_SCL, 201 HOLE1, 202 HOLE2, 203 HOLE3, 204 HOLE4

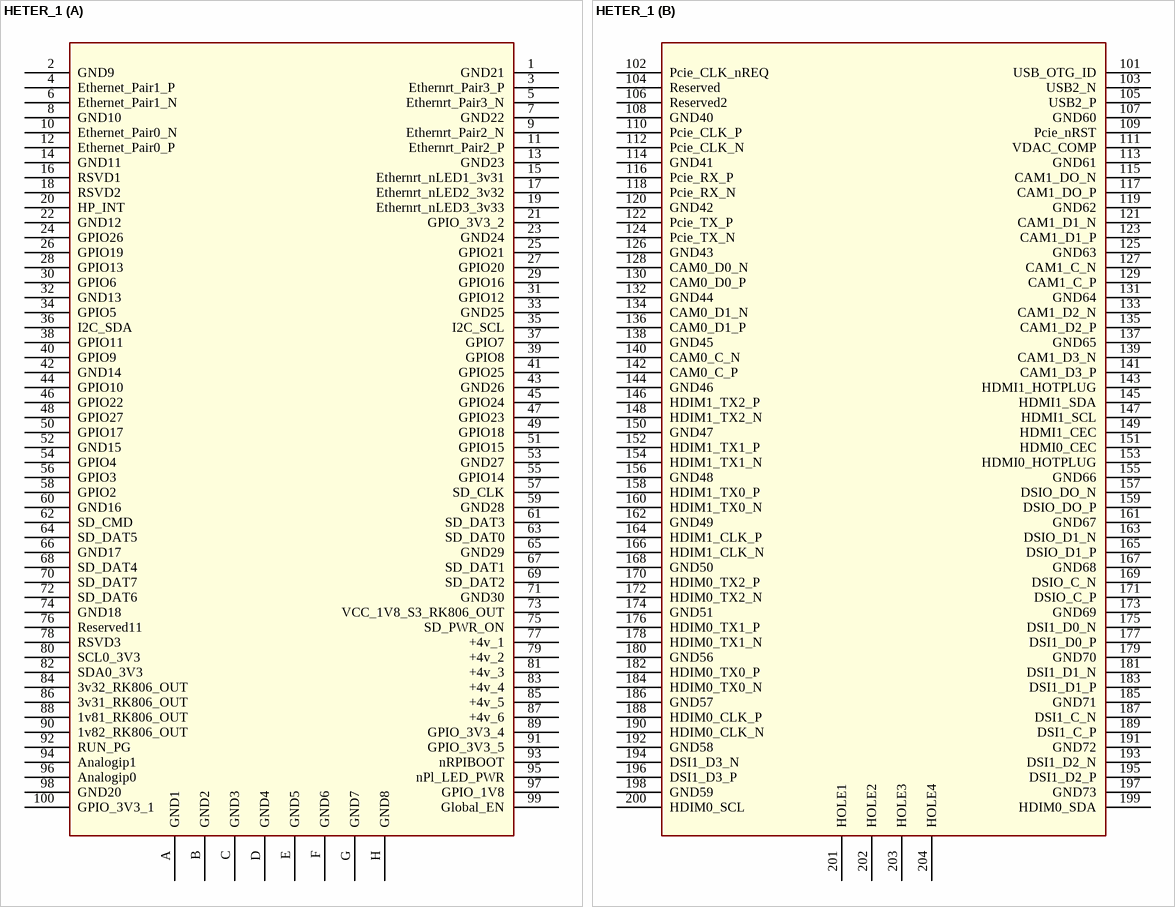
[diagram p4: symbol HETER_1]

## HETER_1
designator U?
Altium-Right: 296; Altium-Bottom: 529
part A pins: 1 GND21, 2 GND9, 3 Ethernrt_Pair3_P, 4 Ethernet_Pair1_P, 5 Ethernrt_Pair3_N, 6 Ethernet_Pair1_N, 7 GND22, 8 GND10, 9 Ethernrt_Pair2_N, 10 Ethernet_Pair0_N, 11 Ethernrt_Pair2_P, 12 Ethernet_Pair0_P, 13 GND23, 14 GND11, 15 Ethernrt_nLED1_3v31, 16 RSVD1, 17 Ethernrt_nLED2_3v32, 18 RSVD2, 19 Ethernrt_nLED3_3v33, 20 HP_INT, 21 GPIO_3V3_2, 22 GND12, 23 GND24, 24 GPIO26, 25 GPIO21, 26 GPIO19, 27 GPIO20, 28 GPIO13, 29 GPIO16, 30 GPIO6, 31 GPIO12, 32 GND13, 33 GND25, 34 GPIO5, 35 I2C_SCL, 36 I2C_SDA, 37 GPIO7, 38 GPIO11, 39 GPIO8, 40 GPIO9, 41 GPIO25, 42 GND14, 43 GND26, 44 GPIO10, 45 GPIO24, 46 GPIO22, 47 GPIO23, 48 GPIO27, 49 GPIO18, 50 GPIO17, 51 GPIO15, 52 GND15, 53 GND27, 54 GPIO4, 55 GPIO14, 56 GPIO3, 57 SD_CLK, 58 GPIO2, 59 GND28, 60 GND16, 61 SD_DAT3, 62 SD_CMD, 63 SD_DAT0, 64 SD_DAT5, 65 GND29, 66 GND17, 67 SD_DAT1, 68 SD_DAT4, 69 SD_DAT2, 70 SD_DAT7, 71 GND30, 72 SD_DAT6, 73 VCC_1V8_S3_RK806_OUT, 74 GND18, 75 SD_PWR_ON, 76 Reserved11, 77 +4v_1, 78 RSVD3, 79 +4v_2, 80 SCL0_3V3, 81 +4v_3, 82 SDA0_3V3, 83 +4v_4, 84 3v32_RK806_OUT, 85 +4v_5, 86 3v31_RK806_OUT, 87 +4v_6, 88 1v81_RK806_OUT, 89 GPIO_3V3_4, 90 1v82_RK806_OUT, 91 GPIO_3V3_5, 92 RUN_PG, 93 nRPIBOOT, 94 Analogip1, 95 nPl_LED_PWR, 96 Analogip0, 97 GPIO_1V8, 98 GND20, 99 Global_EN, 100 GPIO_3V3_1, A GND1, B GND2, C GND3, D GND4, E GND5, F GND6, G GND7, H GND8
part B pins: 101 USB_OTG_ID, 102 Pcie_CLK_nREQ, 103 USB2_N, 104 Reserved, 105 USB2_P, 106 Reserved2, 107 GND60, 108 GND40, 109 Pcie_nRST, 110 Pcie_CLK_P, 111 VDAC_COMP, 112 Pcie_CLK_N, 113 GND61, 114 GND41, 115 CAM1_DO_N, 116 Pcie_RX_P, 117 CAM1_DO_P, 118 Pcie_RX_N, 119 GND62, 120 GND42, 121 CAM1_D1_N, 122 Pcie_TX_P, 123 CAM1_D1_P, 124 Pcie_TX_N, 125 GND63, 126 GND43, 127 CAM1_C_N, 128 CAM0_D0_N, 129 CAM1_C_P, 130 CAM0_D0_P, 131 GND64, 132 GND44, 133 CAM1_D2_N, 134 CAM0_D1_N, 135 CAM1_D2_P, 136 CAM0_D1_P, 137 GND65, 138 GND45, 139 CAM1_D3_N, 140 CAM0_C_N, 141 CAM1_D3_P, 142 CAM0_C_P, 143 HDMI1_HOTPLUG, 144 GND46, 145 HDMI1_SDA, 146 HDIM1_TX2_P, 147 HDMI1_SCL, 148 HDIM1_TX2_N, 149 HDMI1_CEC, 150 GND47, 151 HDMI0_CEC, 152 HDIM1_TX1_P, 153 HDMI0_HOTPLUG, 154 HDIM1_TX1_N, 155 GND66, 156 GND48, 157 DSIO_DO_N, 158 HDIM1_TX0_P, 159 DSIO_DO_P, 160 HDIM1_TX0_N, 161 GND67, 162 GND49, 163 DSIO_D1_N, 164 HDIM1_CLK_P, 165 DSIO_D1_P, 166 HDIM1_CLK_N, 167 GND68, 168 GND50, 169 DSIO_C_N, 170 HDIM0_TX2_P, 171 DSIO_C_P, 172 HDIM0_TX2_N, 173 GND69, 174 GND51, 175 DSI1_D0_N, 176 HDIM0_TX1_P, 177 DSI1_D0_P, 178 HDIM0_TX1_N, 179 GND70, 180 GND56, 181 DSI1_D1_N, 182 HDIM0_TX0_P, 183 DSI1_D1_P, 184 HDIM0_TX0_N, 185 GND71, 186 GND57, 187 DSI1_C_N, 188 HDIM0_CLK_P, 189 DSI1_C_P, 190 HDIM0_CLK_N, 191 GND72, 192 GND58, 193 DSI1_D2_N, 194 DSI1_D3_N, 195 DSI1_D2_P, 196 DSI1_D3_P, 197 GND73, 198 GND59, 199 HDIM0_SDA, 200 HDIM0_SCL, 201 HOLE1, 202 HOLE2, 203 HOLE3, 204 HOLE4

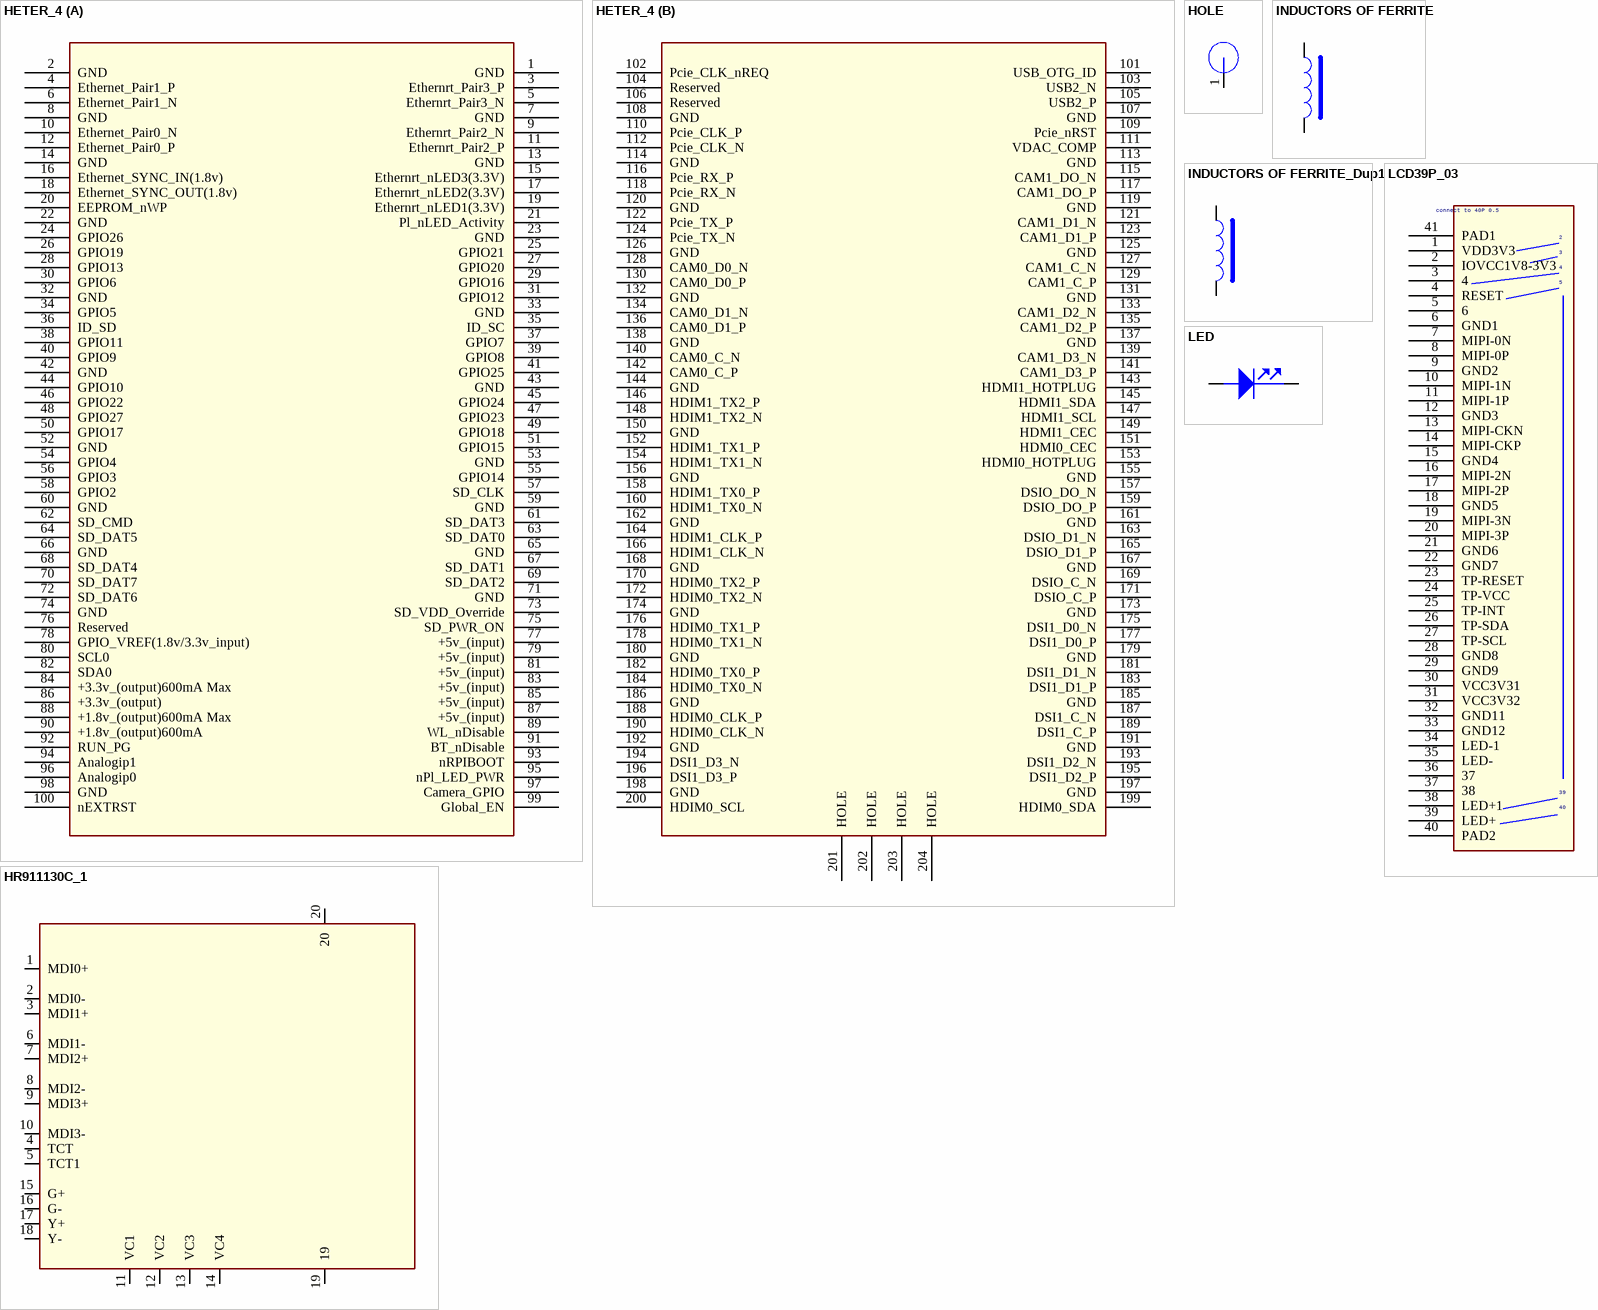
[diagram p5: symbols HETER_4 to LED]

## HETER_4
designator U?
Altium-Right: 296; Altium-Bottom: 529
part A pins: 1 GND, 2 GND, 3 Ethernrt_Pair3_P, 4 Ethernet_Pair1_P, 5 Ethernrt_Pair3_N, 6 Ethernet_Pair1_N, 7 GND, 8 GND, 9 Ethernrt_Pair2_N, 10 Ethernet_Pair0_N, 11 Ethernrt_Pair2_P, 12 Ethernet_Pair0_P, 13 GND, 14 GND, 15 Ethernrt_nLED3(3.3V), 16 Ethernet_SYNC_IN(1.8v), 17 Ethernrt_nLED2(3.3V), 18 Ethernet_SYNC_OUT(1.8v), 19 Ethernrt_nLED1(3.3V), 20 EEPROM_nWP, 21 Pl_nLED_Activity, 22 GND, 23 GND, 24 GPIO26, 25 GPIO21, 26 GPIO19, 27 GPIO20, 28 GPIO13, 29 GPIO16, 30 GPIO6, 31 GPIO12, 32 GND, 33 GND, 34 GPIO5, 35 ID_SC, 36 ID_SD, 37 GPIO7, 38 GPIO11, 39 GPIO8, 40 GPIO9, 41 GPIO25, 42 GND, 43 GND, 44 GPIO10, 45 GPIO24, 46 GPIO22, 47 GPIO23, 48 GPIO27, 49 GPIO18, 50 GPIO17, 51 GPIO15, 52 GND, 53 GND, 54 GPIO4, 55 GPIO14, 56 GPIO3, 57 SD_CLK, 58 GPIO2, 59 GND, 60 GND, 61 SD_DAT3, 62 SD_CMD, 63 SD_DAT0, 64 SD_DAT5, 65 GND, 66 GND, 67 SD_DAT1, 68 SD_DAT4, 69 SD_DAT2, 70 SD_DAT7, 71 GND, 72 SD_DAT6, 73 SD_VDD_Override, 74 GND, 75 SD_PWR_ON, 76 Reserved, 77 +5v_(input), 78 GPIO_VREF(1.8v/3.3v_input), 79 +5v_(input), 80 SCL0, 81 +5v_(input), 82 SDA0, 83 +5v_(input), 84 +3.3v_(output)600mA Max, 85 +5v_(input), 86 +3.3v_(output), 87 +5v_(input), 88 +1.8v_(output)600mA Max, 89 WL_nDisable, 90 +1.8v_(output)600mA , 91 BT_nDisable, 92 RUN_PG, 93 nRPIBOOT, 94 Analogip1, 95 nPl_LED_PWR, 96 Analogip0, 97 Camera_GPIO, 98 GND, 99 Global_EN, 100 nEXTRST
part B pins: 101 USB_OTG_ID, 102 Pcie_CLK_nREQ, 103 USB2_N, 104 Reserved, 105 USB2_P, 106 Reserved, 107 GND, 108 GND, 109 Pcie_nRST, 110 Pcie_CLK_P, 111 VDAC_COMP, 112 Pcie_CLK_N, 113 GND, 114 GND, 115 CAM1_DO_N, 116 Pcie_RX_P, 117 CAM1_DO_P, 118 Pcie_RX_N, 119 GND, 120 GND, 121 CAM1_D1_N, 122 Pcie_TX_P, 123 CAM1_D1_P, 124 Pcie_TX_N, 125 GND, 126 GND, 127 CAM1_C_N, 128 CAM0_D0_N, 129 CAM1_C_P, 130 CAM0_D0_P, 131 GND, 132 GND, 133 CAM1_D2_N, 134 CAM0_D1_N, 135 CAM1_D2_P, 136 CAM0_D1_P, 137 GND, 138 GND, 139 CAM1_D3_N, 140 CAM0_C_N, 141 CAM1_D3_P, 142 CAM0_C_P, 143 HDMI1_HOTPLUG, 144 GND, 145 HDMI1_SDA, 146 HDIM1_TX2_P, 147 HDMI1_SCL, 148 HDIM1_TX2_N, 149 HDMI1_CEC, 150 GND, 151 HDMI0_CEC, 152 HDIM1_TX1_P, 153 HDMI0_HOTPLUG, 154 HDIM1_TX1_N, 155 GND, 156 GND, 157 DSIO_DO_N, 158 HDIM1_TX0_P, 159 DSIO_DO_P, 160 HDIM1_TX0_N, 161 GND, 162 GND, 163 DSIO_D1_N, 164 HDIM1_CLK_P, 165 DSIO_D1_P, 166 HDIM1_CLK_N, 167 GND, 168 GND, 169 DSIO_C_N, 170 HDIM0_TX2_P, 171 DSIO_C_P, 172 HDIM0_TX2_N, 173 GND, 174 GND, 175 DSI1_D0_N, 176 HDIM0_TX1_P, 177 DSI1_D0_P, 178 HDIM0_TX1_N, 179 GND, 180 GND, 181 DSI1_D1_N, 182 HDIM0_TX0_P, 183 DSI1_D1_P, 184 HDIM0_TX0_N, 185 GND, 186 GND, 187 DSI1_C_N, 188 HDIM0_CLK_P, 189 DSI1_C_P, 190 HDIM0_CLK_N, 191 GND, 192 GND, 193 DSI1_D2_N, 194 DSI1_D3_N, 195 DSI1_D2_P, 196 DSI1_D3_P, 197 GND, 198 GND, 199 HDIM0_SDA, 200 HDIM0_SCL, 201 HOLE, 202 HOLE, 203 HOLE, 204 HOLE

## HOLE
designator H?
Altium-Right: 20
footprint H3.8MM
pins: 1

## HR911130C_1
designator J?
VAL: J00-0061; DESIG: 10/100 base TX LXT971A; BOI: RJ45; FAB: PULSE; DEV: CON_PULSE_J00-61; Altium-Right: 250; Altium-Bottom: 230
footprint RJ45_PULSE
pins: 1 MDI0+, 2 MDI0-, 3 MDI1+, 4 TCT, 5 TCT1, 6 MDI1-, 7 MDI2+, 8 MDI2-, 9 MDI3+, 10 MDI3-, 11 VC1, 12 VC2, 13 VC3, 14 VC4, 15 G+, 16 G-, 17 Y+, 18 Y-, 19, 20

## INDUCTORS OF FERRITE
designator L?
Altium-Right: 20; Altium-Bottom: 40
pins: 1, 2

## INDUCTORS OF FERRITE_Dup1
designator L?
Altium-Right: 20; Altium-Bottom: 40
pins: 1, 2

## LCD39P_03
designator U?
Altium-Right: 80; Altium-Bottom: 430
pins: 1 VDD3V3, 2 IOVCC1V8-3V3, 3 4, 4 RESET, 5 6, 6 GND1, 7 MIPI-0N, 8 MIPI-0P, 9 GND2, 10 MIPI-1N, 11 MIPI-1P, 12 GND3, 13 MIPI-CKN, 14 MIPI-CKP, 15 GND4, 16 MIPI-2N, 17 MIPI-2P, 18 GND5, 19 MIPI-3N, 20 MIPI-3P, 21 GND6, 22 GND7, 23 TP-RESET, 24 TP-VCC, 25 TP-INT, 26 TP-SDA, 27 TP-SCL, 28 GND8, 29 GND9, 30 VCC3V31, 31 VCC3V32, 32 GND11, 33 GND12, 34 LED-1, 35 LED-, 36 37, 37 38, 38 LED+1, 39 LED+, 40 PAD2, 41 PAD1

## LED
designator LED?
Altium-Right: 40; Altium-Bottom: 20
pins: 1 ANODE, 2 CATHODE

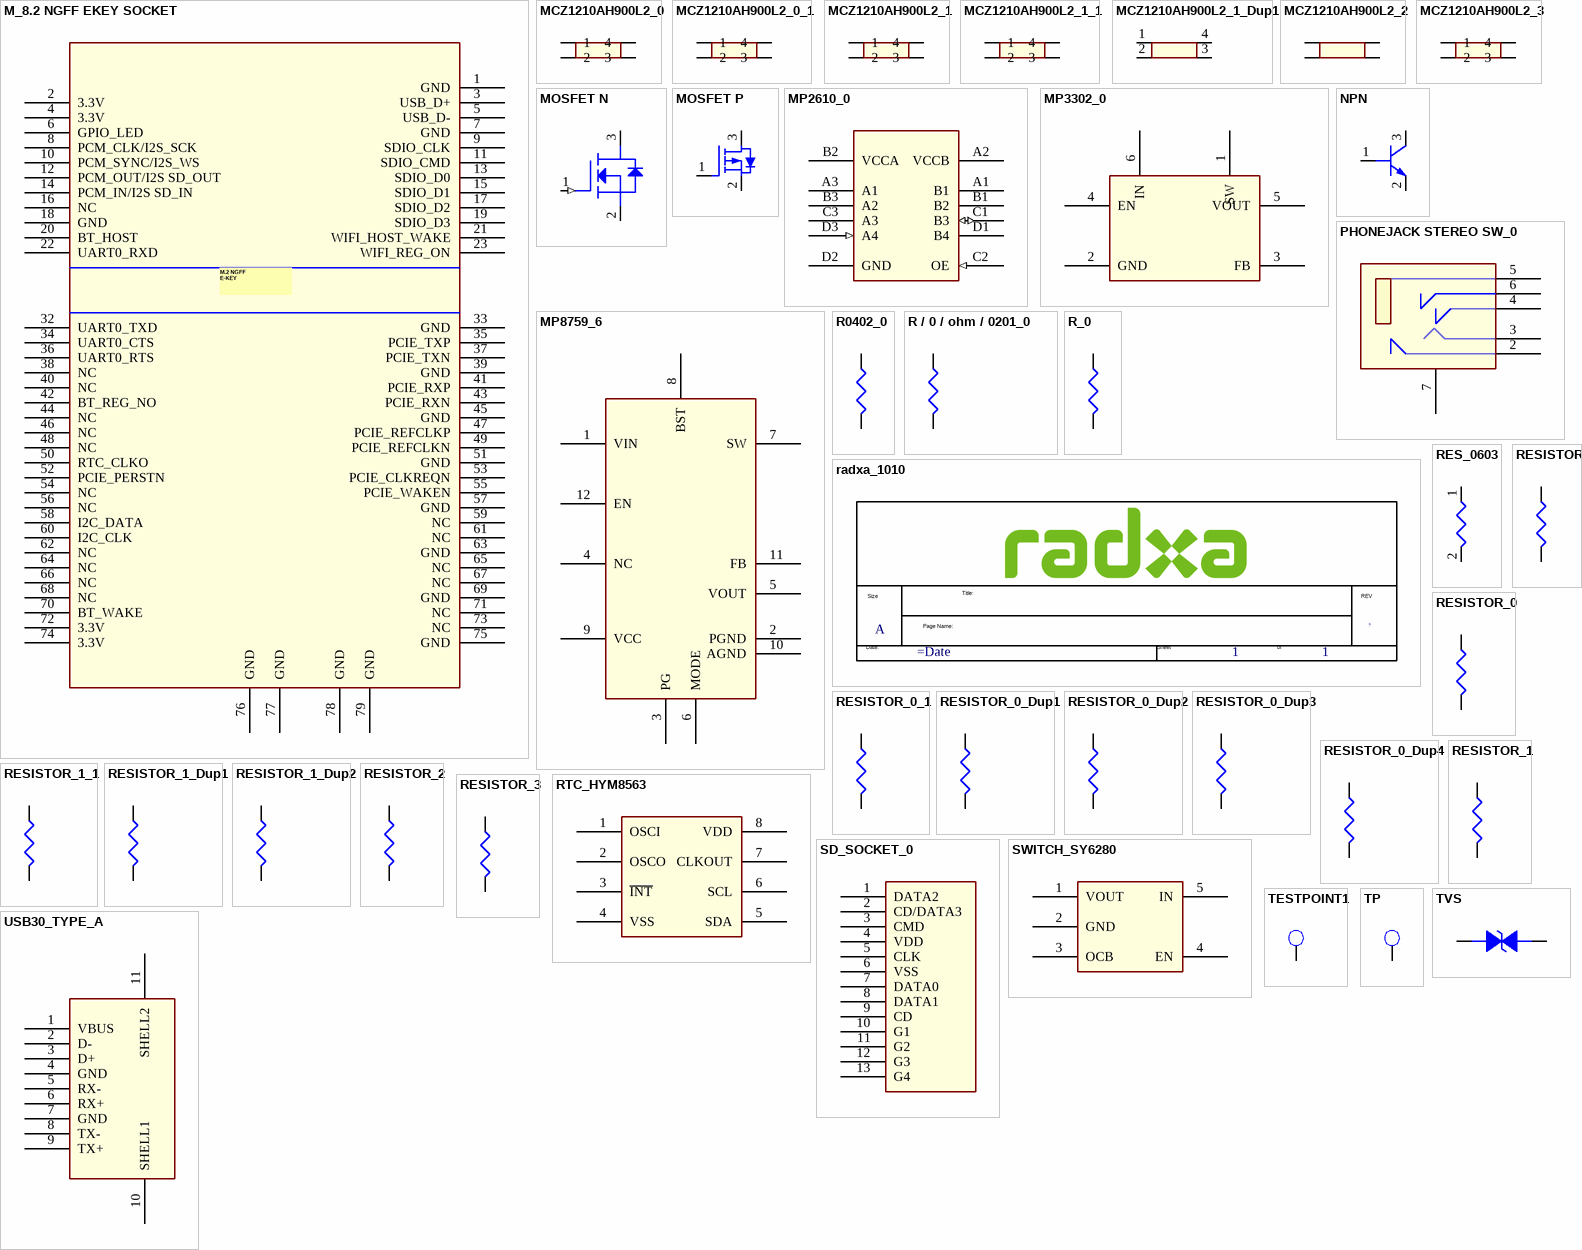
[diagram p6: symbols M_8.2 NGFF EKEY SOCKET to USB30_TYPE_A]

## M_8.2 NGFF EKEY SOCKET
designator U?
Altium-Right: 260; Altium-Bottom: 430
pins: 1 GND, 2 3.3V, 3 USB_D+, 4 3.3V, 5 USB_D-, 6 GPIO_LED, 7 GND, 8 PCM_CLK/I2S_SCK, 9 SDIO_CLK, 10 PCM_SYNC/I2S_WS, 11 SDIO_CMD, 12 PCM_OUT/I2S SD_OUT, 13 SDIO_D0, 14 PCM_IN/I2S SD_IN, 15 SDIO_D1, 16 NC, 17 SDIO_D2, 18 GND, 19 SDIO_D3, 20 BT_HOST, 21 WIFI_HOST_WAKE, 22 UART0_RXD, 23 WIFI_REG_ON, 32 UART0_TXD, 33 GND, 34 UART0_CTS, 35 PCIE_TXP, 36 UART0_RTS, 37 PCIE_TXN, 38 NC, 39 GND, 40 NC, 41 PCIE_RXP, 42 BT_REG_NO, 43 PCIE_RXN, 44 NC, 45 GND, 46 NC, 47 PCIE_REFCLKP, 48 NC, 49 PCIE_REFCLKN, 50 RTC_CLKO, 51 GND, 52 PCIE_PERSTN, 53 PCIE_CLKREQN, 54 NC, 55 PCIE_WAKEN, 56 NC, 57 GND, 58 I2C_DATA, 59 NC, 60 I2C_CLK, 61 NC, 62 NC, 63 GND, 64 NC, 65 NC, 66 NC, 67 NC, 68 NC, 69 GND, 70 BT_WAKE, 71 NC, 72 3.3V, 73 NC, 74 3.3V, 75 GND, 76 GND, 77 GND, 78 GND, 79 GND

## MCZ1210AH900L2_0
designator L?
Altium-Right: 30; Altium-Bottom: 10
footprint MCZ1210AH900L2
pins: 1, 2, 3, 4

## MCZ1210AH900L2_0_1
designator L?
Altium-Right: 30; Altium-Bottom: 10
footprint MCZ1210AH900L2
pins: 1, 2, 3, 4

## MCZ1210AH900L2_1
designator L?
Altium-Right: 30; Altium-Bottom: 10
footprint MCZ1210AH900L2
pins: 1, 2, 3, 4

## MCZ1210AH900L2_1_1
designator L?
Altium-Right: 30; Altium-Bottom: 10
footprint MCZ1210AH900L2
pins: 1, 2, 3, 4

## MCZ1210AH900L2_1_Dup1
designator L?
Altium-Right: 30; Altium-Bottom: 10
footprint MCZ1210AH900L2
pins: 1, 2, 3, 4

## MCZ1210AH900L2_2
designator L?
Altium-Right: 30; Altium-Bottom: 10
footprint MCZ1210AH900L2
pins: 1, 2, 3, 4

## MCZ1210AH900L2_3
designator L?
Altium-Right: 30; Altium-Bottom: 10
footprint MCZ1210AH900L2
pins: 1, 2, 3, 4

## MOSFET N
designator Q?
Altium-Right: 50; Altium-Bottom: 40
footprint SOT23
pins: 1 GATE (in), 2 SOURCE, 3 DRAIN

## MOSFET P
designator Q?
Altium-Right: 30; Altium-Bottom: 20
footprint SOT23
pins: 1 GATE, 2 SOURCE, 3 DRAIN

## MP2610_0
designator U?
Altium-Right: 70; Altium-Bottom: 100
pins: A1 B1 (hiz), A2 VCCB (power), A3 A1 (hiz), B1 B2 (hiz), B2 VCCA (power), B3 A2 (hiz), C1 B3 (io), C2 OE (in), C3 A3 (hiz), D1 B4 (hiz), D2 GND (power), D3 A4 (in)

## MP3302_0
designator U?
Altium-Right: 100; Altium-Bottom: 70
footprint sot23-6
pins: 1 SW, 2 GND, 3 FB, 4 EN, 5 VOUT, 6 IN

## MP8759_6
designator U?
Altium-Right: 100; Altium-Bottom: 200
footprint QFN12_2R00X3R00X1R00
pins: 1 VIN, 2 PGND, 3 PG, 4 NC, 5 VOUT, 6 MODE, 7 SW, 8 BST, 9 VCC, 10 AGND, 11 FB, 12 EN

## NPN
designator Q?
Altium-Right: 20
pins: 1 BASE, 2 EMITTER, 3 COLLECTOR

## PHONEJACK STEREO SW_0
designator J?
Altium-Right: 90; Altium-Bottom: 70
pins: 2 DH, 3 R, 4 L, 5 D, 6 HP, 7 NC2

## R0402_0
designator R?
Altium-Right: 20; Altium-Bottom: 30
footprint R0603
pins: 1, 2

## R / 0 / ohm / 0201_0
designator R?
Altium-Right: 20; Altium-Bottom: 30
footprint R0201
pins: 1, 2

## R_0
designator R?
Altium-Right: 20; Altium-Bottom: 30
pins: 1, 2

## radxa_1010
designator *  Page Size: A  Page Number: 1  (hidden comment: *)  (graphical)
Altium-Right: 360; Altium-Bottom: 107

## RES_0603
designator R?
Altium-Right: 20; Altium-Bottom: 30
footprint R0603
pins: 1, 2

## RESISTOR
designator R?
Altium-Right: 20; Altium-Bottom: 30
pins: 1, 2

## RESISTOR_0
designator R?
Altium-Right: 20; Altium-Bottom: 30
footprint R0402
pins: 1, 2

## RESISTOR_0_1
designator R?
Altium-Right: 20; Altium-Bottom: 30
footprint R0402
pins: 1, 2

## RESISTOR_0_Dup1
designator R?
Altium-Right: 20; Altium-Bottom: 30
footprint R0402
pins: 1, 2

## RESISTOR_0_Dup2
designator R?
Altium-Right: 20; Altium-Bottom: 30
footprint R0402
pins: 1, 2

## RESISTOR_0_Dup3
designator R?
Altium-Right: 20; Altium-Bottom: 30
footprint R0402
pins: 1, 2

## RESISTOR_0_Dup4
designator R?
Altium-Right: 20; Altium-Bottom: 30
footprint R0402
pins: 1, 2

## RESISTOR_1
designator R?
Altium-Right: 20; Altium-Bottom: 30
footprint R0402
pins: 1, 2

## RESISTOR_1_1
designator R?
Altium-Right: 20; Altium-Bottom: 30
footprint R0402
pins: 1, 2

## RESISTOR_1_Dup1
designator R?
Altium-Right: 20; Altium-Bottom: 30
footprint R0402
pins: 1, 2

## RESISTOR_1_Dup2
designator R?
Altium-Right: 20; Altium-Bottom: 30
pins: 1, 2

## RESISTOR_2
designator R?
Altium-Right: 20; Altium-Bottom: 30
footprint R0402
pins: 1, 2

## RESISTOR_3
designator R?
Altium-Right: 20; Altium-Bottom: 30
footprint R0402
pins: 1, 2

## RTC_HYM8563
designator U?
Altium-Right: 80
pins: 1 OSCI, 2 OSCO, 3 ~{INT}, 4 VSS, 5 SDA, 6 SCL, 7 CLKOUT, 8 VDD

## SD_SOCKET_0
designator U?
Altium-Right: 60; Altium-Bottom: 140
pins: 1 DATA2, 2 CD/DATA3, 3 CMD, 4 VDD, 5 CLK, 6 VSS, 7 DATA0, 8 DATA1, 9 CD, 10 G1, 11 G2, 12 G3, 13 G4

## SWITCH_SY6280
designator U?
Altium-Right: 70; Altium-Bottom: 60
pins: 1 VOUT, 2 GND, 3 OCB, 4 EN, 5 IN

## TESTPOINT1
designator TP?  (value not drawn)
Altium-Right: 20; Altium-Bottom: 10
footprint TEST
pins: 1

## TP
designator TP?
Altium-Right: 20; Altium-Bottom: 10
footprint TEST
pins: 1

## TVS
designator D?
Altium-Right: 40; Altium-Bottom: 20
footprint E0402N
pins: 1, 2

## USB30_TYPE_A
designator USB?
Altium-Right: 70; Altium-Bottom: 120
footprint USB30
pins: 1 VBUS (power), 2 D-, 3 D+, 4 GND (power), 5 RX-, 6 RX+, 7 GND (power), 8 TX-, 9 TX+, 10 SHELL1, 11 SHELL2

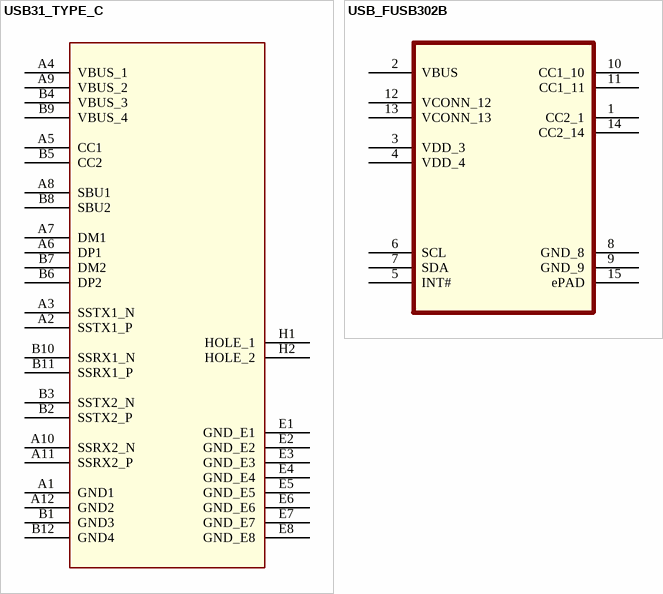
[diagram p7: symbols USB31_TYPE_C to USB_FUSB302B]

## USB31_TYPE_C
designator J?
Altium-Right: 130; Altium-Bottom: 350
pins: A1 GND1, A2 SSTX1_P, A3 SSTX1_N, A4 VBUS_1, A5 CC1, A6 DP1, A7 DM1, A8 SBU1, A9 VBUS_2, A10 SSRX2_N, A11 SSRX2_P, A12 GND2, B1 GND3, B2 SSTX2_P, B3 SSTX2_N, B4 VBUS_3, B5 CC2, B6 DP2, B7 DM2, B8 SBU2, B9 VBUS_4, B10 SSRX1_N, B11 SSRX1_P, B12 GND4, E1 GND_E1, E2 GND_E2, E3 GND_E3, E4 GND_E4, E5 GND_E5, E6 GND_E6, E7 GND_E7, E8 GND_E8, H1 HOLE_1, H2 HOLE_2

## USB_FUSB302B
designator U?
Altium-Right: 120; Altium-Bottom: 180
footprint MLP14_2R50X2R50X0R80
pins: 1 CC2_1, 2 VBUS, 3 VDD_3 (power), 4 VDD_4 (power), 5 INT#, 6 SCL, 7 SDA, 8 GND_8 (power), 9 GND_9 (power), 10 CC1_10, 11 CC1_11, 12 VCONN_12, 13 VCONN_13, 14 CC2_14, 15 ePAD (power)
